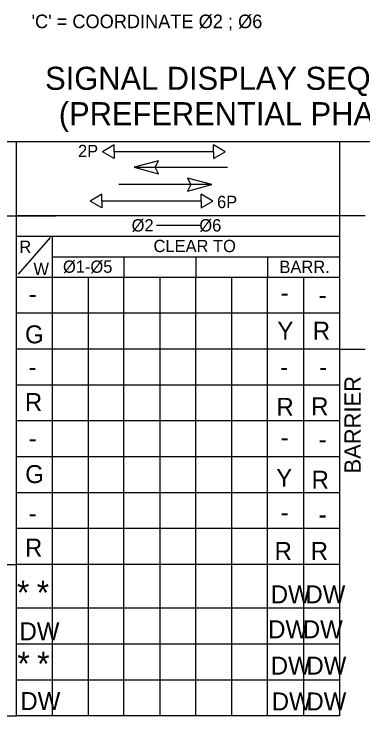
# Model space of a CAD drawing. Extents: x 0 to 3.01, y -0.05 to 1.83.
# Drawn here: x 2.5103 to 2.6475, y 1.2756 to 1.5516 of the extents above; entities that cross this region are included whole.
import ezdxf

# ---------------------------------------------------------------- set-up
doc = ezdxf.new("R2010")
doc.units = 0
for name, color, linetype in [('TR_TS_Border', 7, 'Continuous'), ('TR_TS_Phase1', 7, 'Continuous'), ('TR_TS_Phase2', 7, 'Continuous'), ('TR_TS_Phase3', 7, 'Continuous'), ('TR_TS_Phase4', 7, 'Continuous'), ('TR_TS_Phase5', 7, 'Continuous'), ('TR_TS_Phase6', 7, 'Continuous'), ('TR_TS_Phase7', 7, 'Continuous'), ('TR_TS_Phase8', 7, 'Continuous')]:
    doc.layers.add(name, color=color, linetype=linetype)

msp = doc.modelspace()

# ---------------------------------------------------------------- linework, layer by layer
at = {"layer": 'TR_TS_Border'}
for p, q in [((2.907476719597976, 1.5013454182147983), (2.2983738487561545, 1.5013454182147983)), ((2.5111802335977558, 1.5013455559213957), (2.5111802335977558, 1.27559374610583)), ((2.549707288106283, 1.5001261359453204), (2.545117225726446, 1.4974608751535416)), ((2.549707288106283, 1.4974608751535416), (2.549707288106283, 1.5001261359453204)), ((2.5933045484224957, 1.4974608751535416), (2.5887143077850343, 1.5001261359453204)), ((2.5887143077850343, 1.4974608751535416), (2.5887143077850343, 1.5001261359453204)), ((2.638252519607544, 1.5013455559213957), (2.638252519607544, 1.4198639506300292)), ((2.549707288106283, 1.494795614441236), (2.545117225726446, 1.4974608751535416)), ((2.549707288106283, 1.4974608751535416), (2.549707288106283, 1.494795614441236)), ((2.5887143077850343, 1.4974608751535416), (2.549820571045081, 1.4974608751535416)), ((2.5887143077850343, 1.4974608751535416), (2.5887143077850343, 1.494795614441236)), ((2.5887143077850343, 1.494795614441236), (2.5933045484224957, 1.4974608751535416)), ((2.503587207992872, 1.4722744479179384), (2.5267743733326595, 1.4722744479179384)), ((2.638252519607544, 1.4722744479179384), (2.5111802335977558, 1.4722744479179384)), ((2.6483232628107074, 1.4722744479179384), (2.638252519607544, 1.4722744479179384)), ((2.5662642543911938, 1.468530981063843), (2.583652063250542, 1.468530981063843)), ((2.5111802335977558, 1.4642071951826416), (2.638252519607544, 1.4642071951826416)), ((2.5120237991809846, 1.4492854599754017), (2.524678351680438, 1.4637328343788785)), ((2.5253112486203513, 1.4642071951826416), (2.5253112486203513, 1.27559374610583)), ((2.5253112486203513, 1.4561402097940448), (2.638252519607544, 1.4561402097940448)), ((2.553519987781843, 1.4561402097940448), (2.553519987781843, 1.4480727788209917)), ((2.5817289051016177, 1.4561402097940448), (2.5817289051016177, 1.4480727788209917)), ((2.6099907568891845, 1.4561402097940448), (2.6099907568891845, 1.4480727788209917)), ((2.638252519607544, 1.4480727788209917), (2.5111802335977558, 1.4480727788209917)), ((2.539389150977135, 1.4480727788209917), (2.539389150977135, 1.27559374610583)), ((2.553519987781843, 1.27559374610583), (2.553519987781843, 1.4480727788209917)), ((2.5676510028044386, 1.4480727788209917), (2.5676510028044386, 1.27559374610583)), ((2.5817289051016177, 1.27559374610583), (2.5817289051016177, 1.4480727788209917)), ((2.595859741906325, 1.4480727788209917), (2.595859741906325, 1.27559374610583)), ((2.6099907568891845, 1.27559374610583), (2.6099907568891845, 1.4480727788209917)), ((2.6241215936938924, 1.4480727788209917), (2.6241215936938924, 1.27559374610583)), ((2.638252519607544, 1.433941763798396), (2.5111802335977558, 1.433941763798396)), ((2.638252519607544, 1.4198639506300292), (2.5111802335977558, 1.4198639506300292)), ((2.638252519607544, 1.4198639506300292), (2.638252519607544, 1.27559374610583)), ((2.638252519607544, 1.4198639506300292), (2.6483232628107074, 1.4198639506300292)), ((2.638252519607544, 1.405733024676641), (2.5111802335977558, 1.405733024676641)), ((2.638252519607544, 1.3916020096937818), (2.5111802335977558, 1.3916020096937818)), ((2.638252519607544, 1.3775241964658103), (2.5111802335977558, 1.3775241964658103)), ((2.638252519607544, 1.3633932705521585), (2.5111802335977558, 1.3633932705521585)), ((2.638252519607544, 1.3492622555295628), (2.5111802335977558, 1.3492622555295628)), ((2.506118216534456, 1.3351314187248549), (2.5111802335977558, 1.3351314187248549)), ((2.638252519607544, 1.3351314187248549), (2.5111802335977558, 1.3351314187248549)), ((2.638325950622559, 1.3179863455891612), (2.5112536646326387, 1.3179863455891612)), ((2.638325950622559, 1.3038554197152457), (2.5112536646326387, 1.3038554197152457)), ((2.638325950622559, 1.2897245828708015), (2.5112536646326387, 1.2897245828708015)), ((2.5061917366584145, 1.27559374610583), (2.5112536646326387, 1.27559374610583)), ((2.638325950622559, 1.27559374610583), (2.5112536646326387, 1.27559374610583))]:
    msp.add_line(p, q, dxfattribs=at)
at = {"layer": 'TR_TS_Phase2'}
for p, q in [((2.567145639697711, 1.49394019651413), (2.557521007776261, 1.491348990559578)), ((2.5658129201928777, 1.491348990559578), (2.567145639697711, 1.49394019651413)), ((2.557521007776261, 1.491348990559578), (2.5941680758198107, 1.491348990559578)), ((2.557521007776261, 1.491348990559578), (2.567145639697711, 1.4887576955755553)), ((2.567145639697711, 1.4887576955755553), (2.5658129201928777, 1.491348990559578))]:
    msp.add_line(p, q, dxfattribs=at)
at = {"layer": 'TR_TS_Phase6'}
for p, q in [((2.578469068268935, 1.4871177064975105), (2.579801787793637, 1.4845264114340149)), ((2.588093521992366, 1.4845264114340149), (2.578469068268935, 1.4871177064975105)), ((2.588093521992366, 1.4845264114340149), (2.551446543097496, 1.4845264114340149)), ((2.579801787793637, 1.4845264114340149), (2.578469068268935, 1.4819352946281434)), ((2.578469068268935, 1.4819352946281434), (2.588093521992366, 1.4845264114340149)), ((2.544818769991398, 1.4807221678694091), (2.5402287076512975, 1.4780569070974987)), ((2.544818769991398, 1.4780569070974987), (2.544818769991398, 1.4807221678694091)), ((2.588416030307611, 1.4780569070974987), (2.5838257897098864, 1.4807221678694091)), ((2.5838257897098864, 1.4780569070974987), (2.5838257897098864, 1.4807221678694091)), ((2.544818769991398, 1.475391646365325), (2.5402287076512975, 1.4780569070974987)), ((2.544818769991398, 1.4780569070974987), (2.544818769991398, 1.475391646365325)), ((2.5838257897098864, 1.4780569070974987), (2.544818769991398, 1.4780569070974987)), ((2.5838257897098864, 1.475391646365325), (2.588416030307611, 1.4780569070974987)), ((2.5838257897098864, 1.4780569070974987), (2.5838257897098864, 1.475391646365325))]:
    msp.add_line(p, q, dxfattribs=at)

# ---------------------------------------------------------------- texts
at = {"layer": 'TR_TS_Border'}
for s, height, p in [("'C' = COORDINATE Ø2 ; Ø6", 0.005346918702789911, (2.517182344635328, 1.5460523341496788)), ('SIGNAL DISPLAY SEQUENCE', 0.009062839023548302, (2.5225272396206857, 1.5218125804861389)), ('(PREFERENTIAL PHASING)', 0.009062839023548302, (2.5279138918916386, 1.5078981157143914))]:
    msp.add_text(s, height=height, dxfattribs=at).set_placement(p)
for s, height, rotation, p in [('2P', 0.004840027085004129, 359.99999999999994, (2.5354464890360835, 1.495333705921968)), ('Ø2          Ø6', 0.004840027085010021, 360, (2.5565392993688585, 1.466104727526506)), ('R', 0.004840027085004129, 360, (2.51237816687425, 1.457668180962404)), ('CLEAR TO', 0.004840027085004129, 360, (2.565148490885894, 1.4579846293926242)), ('Ø1-Ø5', 0.004840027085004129, 360, (2.529540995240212, 1.4498646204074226)), ('W', 0.004840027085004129, 360, (2.517924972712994, 1.4489682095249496)), ('BARR.', 0.004840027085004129, 360, (2.6146455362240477, 1.4497767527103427)), ('BARRIER', 0.006449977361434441, 89.99999722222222, (2.6466364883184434, 1.3709455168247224))]:
    msp.add_text(s, height=height, rotation=rotation, dxfattribs=at).set_placement(p)
at = {"layer": 'TR_TS_Phase1'}
for p in [(2.5160214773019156, 1.4380670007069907), (2.615140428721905, 1.4384820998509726), (2.6300702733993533, 1.4376521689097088)]:
    msp.add_text('-', height=0.007050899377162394, dxfattribs=at).set_placement(p)
at = {"layer": 'TR_TS_Phase2'}
for s, p in [('Y', (2.613826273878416, 1.4235648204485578)), ('R', (2.627745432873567, 1.4235648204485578)), ('G', (2.5146096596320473, 1.4221316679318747))]:
    msp.add_text(s, height=0.007050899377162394, rotation=360, dxfattribs=at).set_placement(p)
for s, height, p in [('*', 0.009384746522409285, (2.5114244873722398, 1.3194456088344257)), ('*', 0.009384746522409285, (2.5191950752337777, 1.3193891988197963)), ('DW', 0.007050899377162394, (2.611227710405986, 1.319883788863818)), ('DW', 0.007050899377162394, (2.624857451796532, 1.3199015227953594))]:
    msp.add_text(s, height=height, dxfattribs=at).set_placement(p)
at = {"layer": 'TR_TS_Phase3'}
for p in [(2.5160111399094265, 1.4093552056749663), (2.6149442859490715, 1.4093552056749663), (2.630283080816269, 1.4093552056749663)]:
    msp.add_text('-', height=0.007050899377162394, dxfattribs=at).set_placement(p)
at = {"layer": 'TR_TS_Phase4'}
for p in [(2.514556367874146, 1.3954947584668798), (2.6134718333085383, 1.39363089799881), (2.627106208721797, 1.3938137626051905)]:
    msp.add_text('R', height=0.007050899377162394, rotation=360, dxfattribs=at).set_placement(p)
for p in [(2.5124476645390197, 1.3053682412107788), (2.6101994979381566, 1.3061433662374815), (2.623828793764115, 1.3061433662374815)]:
    msp.add_text('DW', height=0.007050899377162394, dxfattribs=at).set_placement(p)
at = {"layer": 'TR_TS_Phase5'}
for p in [(2.5160214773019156, 1.381242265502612), (2.615140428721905, 1.381657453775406), (2.6300702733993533, 1.380827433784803)]:
    msp.add_text('-', height=0.007050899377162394, dxfattribs=at).set_placement(p)
at = {"layer": 'TR_TS_Phase6'}
for s, height, rotation, p in [('6P', 0.004840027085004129, 359.99999999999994, (2.590116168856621, 1.4753038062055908)), ('G', 0.007050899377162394, 360, (2.514693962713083, 1.36717612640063)), ('Y', 0.007050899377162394, 360, (2.6133781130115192, 1.3657226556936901)), ('R', 0.007050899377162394, 360, (2.627297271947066, 1.3649759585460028))]:
    msp.add_text(s, height=height, rotation=rotation, dxfattribs=at).set_placement(p)
for s, height, p in [('*', 0.009384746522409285, (2.511606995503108, 1.2914965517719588)), ('*', 0.009384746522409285, (2.5193775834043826, 1.2914403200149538)), ('DW', 0.007050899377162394, (2.611227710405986, 1.2918489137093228)), ('DW', 0.007050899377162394, (2.6252469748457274, 1.2918489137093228))]:
    msp.add_text(s, height=height, dxfattribs=at).set_placement(p)
at = {"layer": 'TR_TS_Phase7'}
for p in [(2.5160214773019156, 1.351715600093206), (2.615140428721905, 1.3521307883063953), (2.6300702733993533, 1.3513007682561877)]:
    msp.add_text('-', height=0.007050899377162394, dxfattribs=at).set_placement(p)
at = {"layer": 'TR_TS_Phase8'}
for p in [(2.514594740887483, 1.3382641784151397), (2.612733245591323, 1.336968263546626), (2.6269238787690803, 1.336968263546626)]:
    msp.add_text('R', height=0.007050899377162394, rotation=360, dxfattribs=at).set_placement(p)
for p in [(2.51278068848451, 1.2779356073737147), (2.6116173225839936, 1.277780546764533), (2.6252467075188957, 1.277780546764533)]:
    msp.add_text('DW', height=0.007050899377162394, dxfattribs=at).set_placement(p)

doc.saveas('drawing.dxf')
